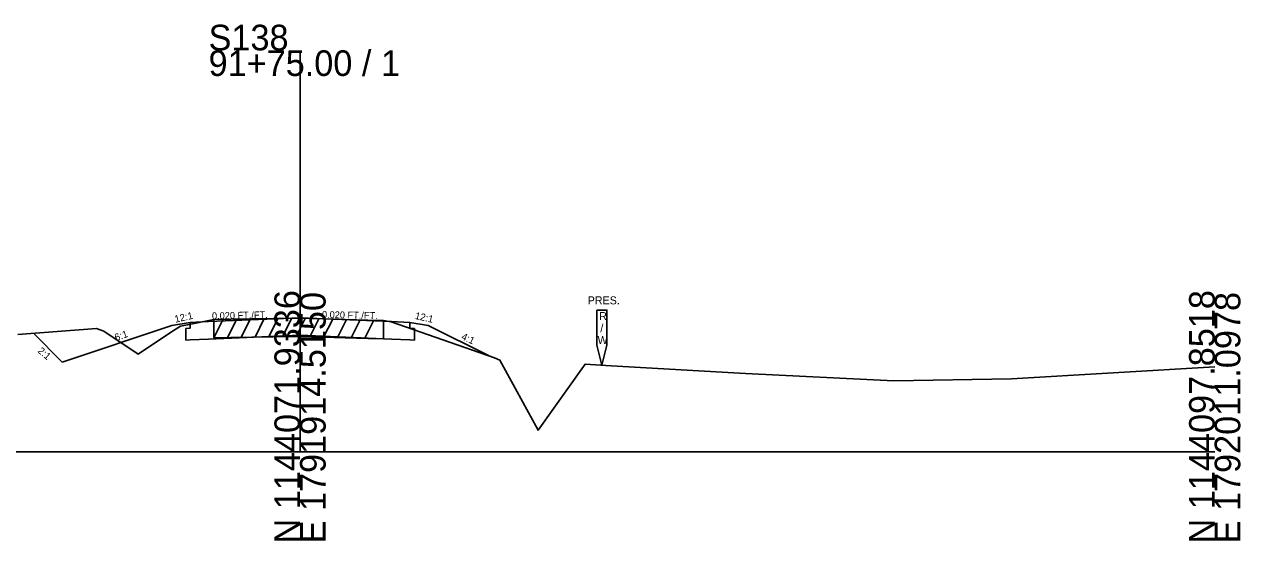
# Model space of a CAD drawing. Extents: x -26 to 1203, y -10 to 19606.
# Drawn here: x 1069.9 to 1202.8, y 3490.3 to 3546.7 of the extents above; entities that cross this region are included whole.
import ezdxf

# ---------------------------------------------------------------- set-up
doc = ezdxf.new("R2010")
doc.units = 0
for name, color, linetype in [('RD_EX_Driveway', 7, 'Continuous'), ('RD_GPK_XS_Cell', 7, 'Continuous'), ('RD_XS_Base', 7, 'Continuous'), ('RD_XS_EarthShd', 7, 'Continuous'), ('RD_XS_ExGround', 7, 'Continuous'), ('RD_XS_ExPaveRet', 7, 'Continuous'), ('RD_XS_ExRW', 7, 'Continuous'), ('RD_XS_Pave', 7, 'Continuous'), ('RD_XS_TX_Slope', 7, 'Continuous')]:
    doc.layers.add(name, color=color, linetype=linetype)

msp = doc.modelspace()

# ---------------------------------------------------------------- linework, layer by layer
at = {"layer": 'RD_GPK_XS_Cell'}
for p, q in [((1100, 3500), (1100, 3543.89)), ((1000, 3500), (1100, 3500)), ((1100, 3500), (1200, 3500))]:
    msp.add_line(p, q, dxfattribs=at)
at = {"layer": 'RD_XS_Base'}
for p, q in [((1088, 3513.52), (1087.5, 3513.5)), ((1087.5, 3512.23), (1087.5, 3513.5)), ((1088, 3513.52), (1088, 3514.16)), ((1112, 3513.52), (1112, 3514.16)), ((1112, 3513.52), (1112.5, 3513.5)), ((1112.5, 3512.23), (1112.5, 3513.5)), ((1088, 3512.25), (1087.5, 3512.23)), ((1088, 3512.25), (1090, 3512.34)), ((1090, 3512.34), (1100, 3512.75)), ((1110, 3512.34), (1100, 3512.75)), ((1112, 3512.25), (1110, 3512.34)), ((1112, 3512.25), (1112.5, 3512.23))]:
    msp.add_line(p, q, dxfattribs=at)
at = {"layer": 'RD_XS_EarthShd'}
for p, q in [((1086, 3513.83), (1074, 3509.83)), ((1088, 3514.16), (1086, 3513.83)), ((1112, 3514.16), (1114, 3513.83)), ((1114, 3513.83), (1120.67, 3510.49)), ((1074, 3509.83), (1070.85, 3512.97))]:
    msp.add_line(p, q, dxfattribs=at)
at = {"layer": 'RD_XS_ExGround'}
msp.add_lwpolyline([(1069.15, 3512.84), (1077.73, 3513.5), (1078.56, 3513.2), (1082.32, 3510.7), (1085.93, 3513.13), (1086.92, 3513.76), (1087.71, 3513.91), (1090.58, 3514.49), (1092.43, 3514.51), (1099.37, 3514.63), (1100, 3514.61), (1107.41, 3514.41), (1109.12, 3514.36), (1109.97, 3514.23), (1121.27, 3510.28), (1121.86, 3510.02), (1126.02, 3502.37), (1131.17, 3509.59), (1134.03, 3509.43), (1148.72, 3508.59), (1164.92, 3507.79), (1177.79, 3507.98), (1200, 3509.32)], dxfattribs=at)
at = {"layer": 'RD_XS_ExPaveRet'}
for p, q in [((1090.58, 3512.49), (1091.58, 3514.5)), ((1090.58, 3512.49), (1090.58, 3514.49)), ((1092.08, 3512.5), (1093.09, 3514.52)), ((1093.58, 3512.53), (1094.59, 3514.55)), ((1095.08, 3512.55), (1096.09, 3514.57)), ((1096.58, 3512.58), (1097.59, 3514.6)), ((1098.08, 3512.61), (1099.09, 3514.63)), ((1099.58, 3512.62), (1100.57, 3514.6)), ((1101.08, 3512.58), (1102.07, 3514.56)), ((1102.58, 3512.54), (1103.57, 3514.52)), ((1104.08, 3512.5), (1105.07, 3514.47)), ((1105.58, 3512.46), (1106.57, 3514.43)), ((1107.08, 3512.42), (1108.07, 3514.39)), ((1109.12, 3514.36), (1109.12, 3512.36)), ((1090.58, 3512.49), (1092.43, 3512.51)), ((1092.43, 3512.51), (1099.37, 3512.63)), ((1099.37, 3512.63), (1100, 3512.61)), ((1100, 3512.61), (1107.41, 3512.41)), ((1107.41, 3512.41), (1109.12, 3512.36))]:
    msp.add_line(p, q, dxfattribs=at)
at = {"layer": 'RD_XS_ExRW'}
msp.add_lwpolyline([(1132.45, 3515.5), (1133.55, 3515.5), (1133.55, 3511.67), (1133, 3509.49), (1132.45, 3511.67)], close=True, dxfattribs=at)
at = {"layer": 'RD_XS_Pave'}
for p, q in [((1088, 3514.16), (1090, 3514.24)), ((1090, 3514.24), (1100, 3514.66)), ((1110, 3514.24), (1100, 3514.66)), ((1112, 3514.16), (1110, 3514.24))]:
    msp.add_line(p, q, dxfattribs=at)

# ---------------------------------------------------------------- texts
at = {"layer": 'RD_EX_Driveway'}
msp.add_text('550.31', height=0.0975, rotation=90, dxfattribs=at).set_placement((1100.1, 3514.61))
at = {"layer": 'RD_GPK_XS_Cell'}
for s, p in [('S138', (1090, 3543.89)), ('91+75.00 / 1', (1090, 3541.09))]:
    msp.add_text(s, height=2.8, dxfattribs=at).set_placement(p)
for s, p in [('N 1144071.9336', (1100, 3490)), ('N 1144097.8518', (1200, 3490)), ('E 1791914.5150', (1102.8, 3490)), ('E 1792011.0978', (1202.8, 3490))]:
    msp.add_text(s, height=2.8, rotation=90, dxfattribs=at).set_placement(p)
at = {"layer": 'RD_XS_ExRW'}
for s, p in [('PRES.', (1131.45, 3516.13)), ('R', (1132.71, 3514.41)), ('/', (1132.83, 3513.1)), ('W', (1132.53, 3511.79))]:
    msp.add_text(s, height=0.875, dxfattribs=at).set_placement(p)
at = {"layer": 'RD_XS_TX_Slope'}
for s, height, rotation, p in [('12:1', 0.778, 12.7511, (1086.38, 3514.12)), ('0.020 FT./FT.', 0.7518, 1.1916, (1090.38, 3514.5)), ('0.020 FT./FT.', 0.7518, 358.8084, (1102.39, 3514.65)), ('12:1', 0.778, 347.2489, (1112.51, 3514.55)), ('6:1', 0.778, 19.3982, (1079.89, 3512.11)), ('4:1', 0.778, 335.081, (1117.56, 3512.35)), ('2:1', 0.778, 319.3411, (1071.25, 3510.95))]:
    msp.add_text(s, height=height, rotation=rotation, dxfattribs=at).set_placement(p)

doc.saveas('drawing.dxf')
